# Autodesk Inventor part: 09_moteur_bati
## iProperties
Created: 2002-11
Part Number: 09_moteur_bati
Material: Par défaut
Document SubType Name: Modélisation
Designer: FIEVET
Control State: 0
Master: False
Checked Out: False
Shininess: 60.0
Length Units: 11269
Angle Units: 11279
Time Units: 11290
Mass Units: 11283
Length Display Precision: 3
Angle Display Precision: 2
Compacted: True
Density: 0.0
Volumn: 0.0
Area: 0.0
PropertySet Name: Model Information
Author: FIEVET
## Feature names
1. Révolution1 [Revolution]
2. Extrusion1
3. Extrusion2
4. Perçage1 [Hole]
5. Extrusion3
6. Révolution2 [Revolution]
7. Extrusion4
8. Extrusion5
9. Extrusion6
